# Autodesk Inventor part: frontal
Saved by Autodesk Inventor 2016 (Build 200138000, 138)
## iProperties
Created: 2013-03
Part Number: frontal
Material: Generic
Document SubType Name: Modeling
Designer: julian.chica
Density: 1 g/cm^3
Appearance: Default
Author: julian.chica
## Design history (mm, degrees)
derived "Parlante_INICIAL.ipt"
feature "frontal::Parlante_INICIAL.ipt" dims "d0" = 10
tag "TaggingFeature1"
body "Solid1"
